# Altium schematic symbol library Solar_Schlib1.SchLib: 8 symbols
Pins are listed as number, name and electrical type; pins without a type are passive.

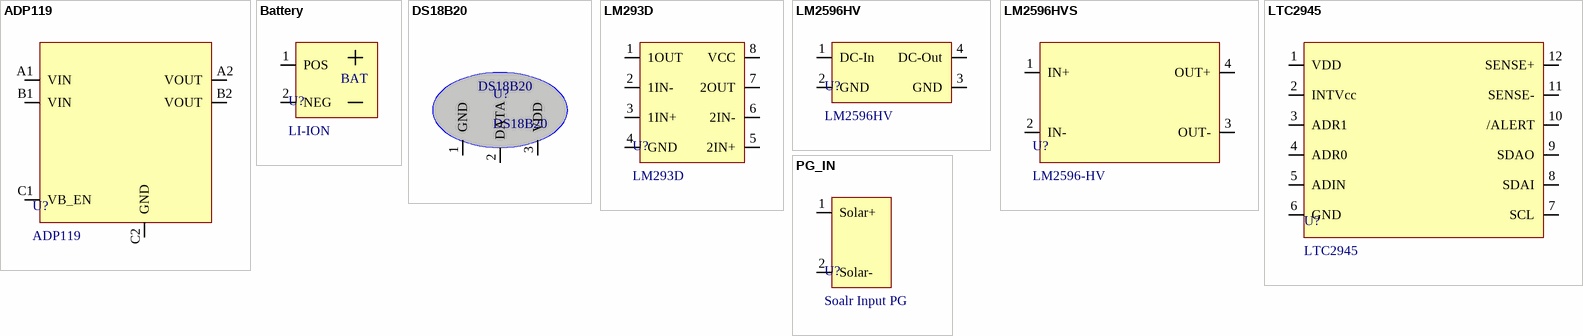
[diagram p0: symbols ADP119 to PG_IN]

## ADP119
designator U?
pins: A1 VIN (power), A2 VOUT (power), B1 VIN (power), B2 VOUT (power), C1 VB_EN (power), C2 GND (power)

## Battery
designator U?, comment LI-ION
Li Ion Battery 3.7V
pins: 1 POS (power), 2 NEG (power)

## DS18B20
designator U?
On Board Temperature Sensor
pins: 1 GND (power), 2 DATA (power), 3 VDD (power)

## LM293D
designator U?
Dual Differential Comparators
pins: 1 1OUT (power), 2 1IN- (power), 3 1IN+ (power), 4 GND (power), 5 2IN+ (power), 6 2IN- (power), 7 2OUT (power), 8 VCC (power)

## LM2596HV
designator U?
DC DC Adjustable Buck converter input upto 60V
footprint LM2596HVS DC-DC step-down module
pins: 1 DC-In (power), 2 GND (power), 3 GND (power), 4 DC-Out (power)

## LM2596HVS
designator U?, comment LM2596-HV
DC DC Buck converter 5V output
pins: 1 IN+ (power), 2 IN- (power), 3 OUT- (power), 4 OUT+ (power)

## LTC2945
designator U?
V I P Monitor I2C Interface
pins: 1 VDD (power), 2 INTVcc (power), 3 ADR1 (power), 4 ADR0 (power), 5 ADIN (power), 6 GND (power), 7 SCL (power), 8 SDAI (power), 9 SDAO (power), 10 /ALERT (power), 11 SENSE- (power), 12 SENSE+ (power)

## PG_IN
designator U?, comment Soalr Input PG
pins: 1 Solar+ (power), 2 Solar- (power)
